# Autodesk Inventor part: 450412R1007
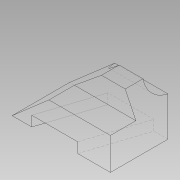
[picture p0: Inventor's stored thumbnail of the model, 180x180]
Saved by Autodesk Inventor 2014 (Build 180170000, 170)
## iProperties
Created: 2015-04
Part Number: 450412R1007
Material: Generic
Document SubType Name: Modeling
Designer: 203-15
Density: 1 g/cm^3
Appearance: Default
Author: 203-15
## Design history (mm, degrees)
sketch "스케치2"
  geometry: L1 (0, 0)-(-135, 0); L2 (-135, 0)-(-135, 89); L3 (-135, 89)-(-102.383, 89); L4 (-102.383, 89)-(0, 0)
  constraints: 8 end point, 1 horizontal, 1 parallel, 1 perpendicular
  dimensions: "d0" = 135 distance of L1.start L1.end; "d1" = 89 distance of L1.end L2.end; "d2" = 139 deg angle of L1 L4
extrude "돌출1" new body sketch "스케치2" distance "d3" = 79; taper "d4" = 0 deg
sketch "스케치3"
  geometry: L1 (89, 0)-(0, 0) reference; L2 (89, 0)-(89, 79) reference; L3 (0, 79)-(89, 79) reference; L4 (0, 0)-(0, 79) reference; L5 (45, 0)-(45, 35); L6 (45, 35)-(0, 20.379); L7 (0, 0)-(45, 0); L8 (0, 20.379)-(0, 0); C1 r 44 at (-8, 88)
  constraints: 8 end point, 3 point on line, 1 centre point, 1 collinear, 1 parallel, 1 perpendicular
  dimensions: "d5" = 44 distance between parallel lines of L2 L5; "d6" = 72 deg angle of L6 L5; "d7" = 35 distance of L5.start L5.end; "d8" = 44 radius of C1; "d9" = 8 distance from line of C1.centre L4; "d10" = 9 distance from line of L3 C1.centre
extrude "돌출2" cut sketch "스케치3" stored distance "d11" = 79; taper "d12" = 0 deg
sketch "스케치4"
  geometry: L1 (50.616, 0)-(0, 0) reference; L2 (0, 0)-(0, 79) reference; L3 (27, 0)-(52.669, 79); L4 (0, 79)-(62.04, 79) reference; L5 (62.04, 79)-(135, 79) reference; L6 (90.088, 0)-(115.756, 79); L7 (52.669, 79)-(115.756, 79); L8 (90.088, 0)-(27, 0)
  constraints: 8 end point, 4 point on line, 2 parallel, 1 collinear
  dimensions: "d13" = 27 distance of L1.end L3.start; "d14" = 72 deg angle of L4 L3; "d15" = 60 distance between parallel lines of L3 L6
extrude "돌출3" cut sketch "스케치4" distance "d16" = 14; taper "d17" = 0 deg
node "솔리드1"
